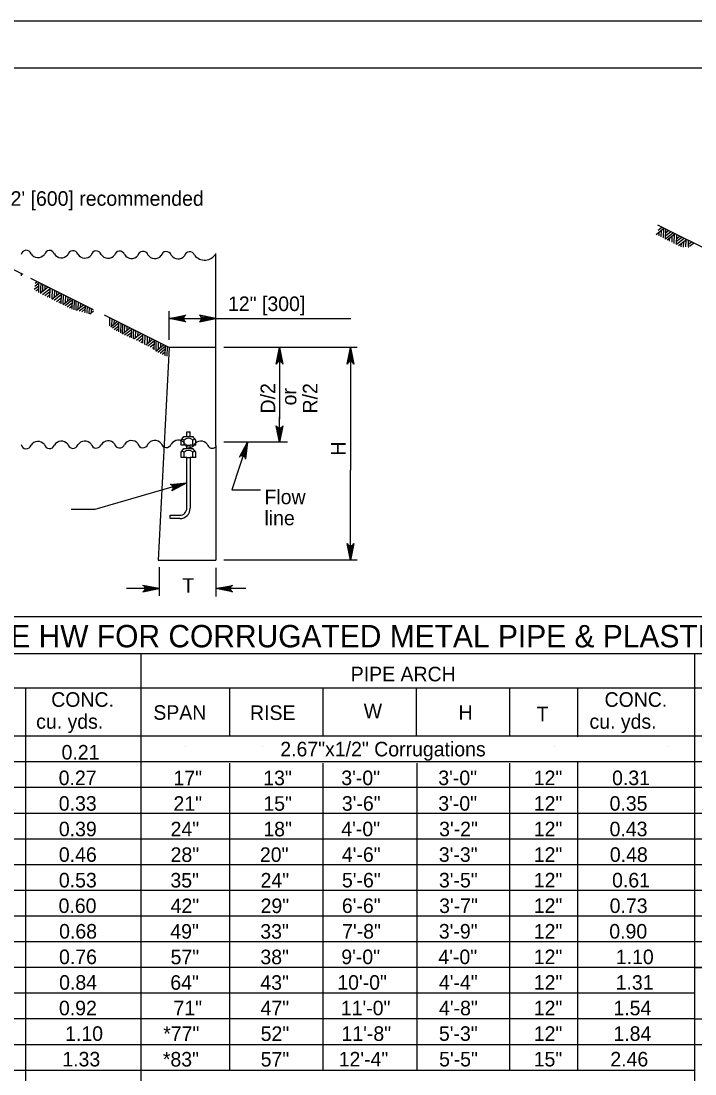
# Model space of a CAD drawing. Extents: x 1083.1 to 1117.1, y 675.4 to 741.4.
# Drawn here: x 1090.68 to 1097.9, y 730.07 to 741.35 of the extents above; entities that cross this region are included whole.
import ezdxf

# ---------------------------------------------------------------- set-up
doc = ezdxf.new("R2010")
doc.units = 0
doc.layers.add('Level 1', color=7, linetype='Continuous')

msp = doc.modelspace()

# ---------------------------------------------------------------- linework, layer by layer
at = {"layer": 'Level 1'}
for p, q in [((1097.48, 739.068), (1097.563, 739.135)), ((1098.803, 738.515), (1097.497, 739.168)), ((1097.503, 739.115), (1097.542, 739.146)), ((1097.534, 739.041), (1097.537, 739.114)), ((1097.558, 739.03), (1097.561, 739.133)), ((1097.579, 739.019), (1097.583, 739.126)), ((1097.581, 739.085), (1097.612, 739.11)), ((1097.511, 739.053), (1097.513, 739.095)), ((1097.579, 739.022), (1097.66, 739.086)), ((1097.58, 739.053), (1097.637, 739.098)), ((1097.597, 739.01), (1097.681, 739.076)), ((1097.624, 738.996), (1097.626, 739.032)), ((1097.65, 738.984), (1097.652, 739.053)), ((1097.674, 738.971), (1097.677, 739.073)), ((1097.698, 738.959), (1097.701, 739.066)), ((1097.698, 738.962), (1097.779, 739.027)), ((1097.699, 738.995), (1097.754, 739.039)), ((1097.701, 739.026), (1097.731, 739.051)), ((1097.721, 738.948), (1097.804, 739.014)), ((1097.773, 738.931), (1097.775, 738.991)), ((1097.798, 738.935), (1097.8, 739.011)), ((1097.825, 738.939), (1097.827, 739.003)), ((1090.698, 738.638), (1090.069, 738.953)), ((1097.748, 738.934), (1097.75, 738.971)), ((1097.824, 738.932), (1097.826, 738.933)), ((1097.825, 738.962), (1097.857, 738.988)), ((1097.836, 738.941), (1097.881, 738.976)), ((1092.764, 736.807), (1092.764, 738.863)), ((1090.681, 738.626), (1090.682, 738.646)), ((1091.452, 738.261), (1090.782, 738.596)), ((1090.823, 738.514), (1090.868, 738.55)), ((1090.827, 738.546), (1090.849, 738.563)), ((1090.865, 738.446), (1090.868, 738.553)), ((1090.888, 738.493), (1090.89, 738.542)), ((1090.818, 738.48), (1090.867, 738.519)), ((1090.833, 738.462), (1090.866, 738.488)), ((1090.881, 738.438), (1090.965, 738.505)), ((1090.887, 738.442), (1090.888, 738.493)), ((1090.907, 738.425), (1090.987, 738.488)), ((1090.909, 738.46), (1090.911, 738.532)), ((1090.932, 738.413), (1090.986, 738.456)), ((1090.933, 738.479), (1090.934, 738.52)), ((1090.984, 738.387), (1090.987, 738.493)), ((1091.007, 738.375), (1091.09, 738.442)), ((1091.009, 738.377), (1091.012, 738.481)), ((1091.031, 738.364), (1091.11, 738.427)), ((1091.035, 738.398), (1091.037, 738.468)), ((1091.059, 738.418), (1091.06, 738.457)), ((1091.107, 738.325), (1091.11, 738.432)), ((1090.956, 738.401), (1090.985, 738.424)), ((1091.055, 738.351), (1091.109, 738.394)), ((1091.081, 738.339), (1091.108, 738.361)), ((1091.126, 738.316), (1091.209, 738.383)), ((1091.128, 738.318), (1091.131, 738.421)), ((1091.147, 738.305), (1091.228, 738.37)), ((1091.152, 738.337), (1091.155, 738.41)), ((1091.171, 738.293), (1091.227, 738.339)), ((1091.178, 738.357), (1091.179, 738.398)), ((1091.225, 738.266), (1091.228, 738.373)), ((1091.246, 738.26), (1091.25, 738.362)), ((1091.265, 738.256), (1091.268, 738.353)), ((1091.271, 738.255), (1091.346, 738.314)), ((1091.289, 738.269), (1091.292, 738.341)), ((1091.314, 738.289), (1091.316, 738.329)), ((1091.194, 738.282), (1091.226, 738.308)), ((1091.298, 738.248), (1091.365, 738.301)), ((1091.326, 738.24), (1091.364, 738.27)), ((1091.354, 738.232), (1091.363, 738.24)), ((1091.363, 738.23), (1091.365, 738.304)), ((1091.385, 738.244), (1091.387, 738.294)), ((1091.385, 738.224), (1091.385, 738.244)), ((1091.406, 738.217), (1091.408, 738.283)), ((1091.412, 738.216), (1091.452, 738.248)), ((1091.43, 738.231), (1091.431, 738.271)), ((1092.263, 737.856), (1091.569, 738.202)), ((1092.263, 737.939), (1092.263, 738.245)), ((1091.626, 738.09), (1091.628, 738.173)), ((1091.638, 738.079), (1091.706, 738.134)), ((1091.649, 738.089), (1091.652, 738.161)), ((1091.655, 738.066), (1091.725, 738.121)), ((1091.675, 738.109), (1091.676, 738.149)), ((1091.675, 738.051), (1091.724, 738.09)), ((1091.722, 738.023), (1091.725, 738.124)), ((1091.744, 738.012), (1091.747, 738.114)), ((1091.762, 738.003), (1091.765, 738.104)), ((1091.786, 738.02), (1091.789, 738.093)), ((1092.423, 738.19), (1092.263, 738.168)), ((1092.417, 738.179), (1092.263, 738.168)), ((1092.263, 738.168), (1094.21, 738.168)), ((1092.416, 738.168), (1092.263, 738.168)), ((1092.418, 738.153), (1092.263, 738.168)), ((1092.425, 738.143), (1092.263, 738.168)), ((1092.601, 738.143), (1092.764, 738.168)), ((1092.603, 738.19), (1092.764, 738.168)), ((1092.608, 738.153), (1092.764, 738.168)), ((1092.609, 738.179), (1092.764, 738.168)), ((1092.61, 738.168), (1092.764, 738.168)), ((1091.696, 738.038), (1091.723, 738.06)), ((1091.764, 738.003), (1091.843, 738.066)), ((1091.786, 737.992), (1091.862, 738.053)), ((1091.811, 737.981), (1091.861, 738.022)), ((1091.812, 738.04), (1091.813, 738.081)), ((1091.834, 737.971), (1091.86, 737.991)), ((1091.859, 737.96), (1091.862, 738.056)), ((1091.881, 737.95), (1091.882, 737.996)), ((1091.882, 737.996), (1091.884, 738.045)), ((1091.885, 737.948), (1091.959, 738.008)), ((1091.903, 737.963), (1091.905, 738.035)), ((1091.911, 737.936), (1091.981, 737.991)), ((1091.927, 737.982), (1091.929, 738.023)), ((1091.979, 737.902), (1091.981, 737.996)), ((1092.003, 737.89), (1092.006, 737.984)), ((1091.936, 737.923), (1091.98, 737.959)), ((1091.96, 737.911), (1091.979, 737.927)), ((1092.011, 737.886), (1092.084, 737.945)), ((1092.029, 737.901), (1092.031, 737.971)), ((1092.034, 737.874), (1092.104, 737.93)), ((1092.053, 737.921), (1092.054, 737.96)), ((1092.059, 737.862), (1092.103, 737.897)), ((1092.083, 737.848), (1092.102, 737.864)), ((1092.102, 737.831), (1092.104, 737.935)), ((1092.12, 737.819), (1092.203, 737.886)), ((1092.122, 737.821), (1092.125, 737.924)), ((1092.141, 737.808), (1092.222, 737.873)), ((1092.147, 737.84), (1092.149, 737.913)), ((1092.172, 737.86), (1092.173, 737.901)), ((1092.219, 737.769), (1092.222, 737.876)), ((1092.241, 737.762), (1092.244, 737.865)), ((1092.263, 737.856), (1092.146, 735.578)), ((1092.165, 737.796), (1092.221, 737.842)), ((1092.188, 737.785), (1092.22, 737.811)), ((1092.764, 737.856), (1092.263, 737.856)), ((1094.277, 737.856), (1092.847, 737.856)), ((1093.421, 737.694), (1093.446, 737.856)), ((1093.431, 737.7), (1093.446, 737.856)), ((1093.446, 737.703), (1093.446, 737.856)), ((1093.457, 737.701), (1093.446, 737.856)), ((1093.468, 737.696), (1093.446, 737.856)), ((1093.446, 737.856), (1093.446, 737.089)), ((1094.18, 737.694), (1094.205, 737.856)), ((1094.191, 737.7), (1094.205, 737.856)), ((1094.205, 737.856), (1094.205, 736.544)), ((1094.205, 737.703), (1094.205, 737.856)), ((1094.216, 737.701), (1094.205, 737.856)), ((1094.227, 737.696), (1094.205, 737.856)), ((1093.446, 736.841), (1093.446, 737.112)), ((1093.423, 737.001), (1093.446, 736.841)), ((1093.434, 736.996), (1093.446, 736.841)), ((1093.47, 737.003), (1093.446, 736.841)), ((1093.46, 736.997), (1093.446, 736.841)), ((1093.446, 736.994), (1093.446, 736.841)), ((1092.392, 736.864), (1092.421, 736.904)), ((1092.392, 736.809), (1092.392, 736.864)), ((1092.421, 736.904), (1092.518, 736.904)), ((1092.422, 736.809), (1092.422, 736.865)), ((1092.452, 736.904), (1092.452, 736.952)), ((1092.452, 736.952), (1092.488, 736.952)), ((1092.488, 736.904), (1092.488, 736.952)), ((1092.548, 736.864), (1092.518, 736.904)), ((1092.518, 736.809), (1092.518, 736.865)), ((1092.548, 736.809), (1092.548, 736.864)), ((1092.452, 736.809), (1092.392, 736.809)), ((1092.392, 736.734), (1092.421, 736.774)), ((1092.392, 736.678), (1092.392, 736.734)), ((1092.421, 736.774), (1092.518, 736.774)), ((1092.422, 736.678), (1092.422, 736.735)), ((1092.452, 736.774), (1092.452, 736.809)), ((1092.452, 736.809), (1092.488, 736.809)), ((1092.488, 736.774), (1092.488, 736.809)), ((1092.548, 736.809), (1092.488, 736.809)), ((1092.548, 736.734), (1092.518, 736.774)), ((1092.518, 736.678), (1092.518, 736.735)), ((1092.548, 736.678), (1092.548, 736.734)), ((1092.764, 736.807), (1092.764, 736.518)), ((1093.529, 736.841), (1092.847, 736.841)), ((1093.029, 736.694), (1093.102, 736.841)), ((1093.041, 736.697), (1093.102, 736.841)), ((1093.056, 736.695), (1093.102, 736.841)), ((1093.066, 736.69), (1093.102, 736.841)), ((1093.075, 736.682), (1093.102, 736.841)), ((1092.452, 736.678), (1092.392, 736.678)), ((1092.452, 736.678), (1092.488, 736.678)), ((1092.452, 736.134), (1092.452, 736.678)), ((1092.548, 736.678), (1092.488, 736.678)), ((1092.488, 736.678), (1092.488, 736.134)), ((1092.764, 736.518), (1092.764, 735.578)), ((1094.205, 735.578), (1094.205, 736.544)), ((1092.289, 736.384), (1092.452, 736.406)), ((1092.298, 736.376), (1092.452, 736.406)), ((1092.304, 736.339), (1092.452, 736.406)), ((1092.305, 736.363), (1092.452, 736.406)), ((1092.306, 736.352), (1092.452, 736.406)), ((1092.272, 736.059), (1092.377, 736.059)), ((1092.272, 736.023), (1092.272, 736.059)), ((1092.377, 736.023), (1092.272, 736.023)), ((1094.183, 735.739), (1094.205, 735.578)), ((1094.194, 735.733), (1094.205, 735.578)), ((1094.23, 735.741), (1094.205, 735.578)), ((1094.219, 735.735), (1094.205, 735.578)), ((1094.205, 735.732), (1094.205, 735.578)), ((1092.146, 735.578), (1092.764, 735.578)), ((1092.157, 735.502), (1092.157, 735.196)), ((1092.764, 735.495), (1092.764, 735.19)), ((1094.277, 735.578), (1092.847, 735.578)), ((1092.157, 735.273), (1091.804, 735.273)), ((1091.995, 735.248), (1092.157, 735.273)), ((1091.997, 735.295), (1092.157, 735.273)), ((1092.001, 735.259), (1092.157, 735.273)), ((1092.002, 735.284), (1092.157, 735.273)), ((1092.004, 735.273), (1092.157, 735.273)), ((1092.924, 735.295), (1092.764, 735.273)), ((1092.918, 735.284), (1092.764, 735.273)), ((1093.085, 735.273), (1092.764, 735.273)), ((1092.917, 735.273), (1092.764, 735.273)), ((1092.92, 735.259), (1092.764, 735.273)), ((1092.926, 735.248), (1092.764, 735.273)), ((1086.66, 734.976), (1103.868, 734.976)), ((1103.868, 734.576), (1086.654, 734.576)), ((1091.964, 721.026), (1091.964, 734.576)), ((1097.894, 721.026), (1097.894, 734.576)), ((1103.868, 734.205), (1086.654, 734.205)), ((1090.728, 721.026), (1090.728, 734.205)), ((1092.913, 733.692), (1092.913, 734.205)), ((1093.913, 733.692), (1093.913, 734.205)), ((1094.912, 733.692), (1094.912, 734.205)), ((1095.912, 733.692), (1095.912, 734.205)), ((1096.642, 733.684), (1096.642, 734.203)), ((1103.868, 733.692), (1086.654, 733.692)), ((1103.868, 733.692), (1086.689, 733.692)), ((1092.437, 733.58), (1092.437, 733.58)), ((1093.265, 733.58), (1093.265, 733.58)), ((1094.26, 733.58), (1094.26, 733.58)), ((1094.386, 733.58), (1094.386, 733.58)), ((1094.407, 733.58), (1094.407, 733.58)), ((1095.265, 733.58), (1095.265, 733.58)), ((1095.39, 733.58), (1095.39, 733.58)), ((1095.412, 733.58), (1095.412, 733.58)), ((1096.396, 733.58), (1096.396, 733.58)), ((1097.604, 733.58), (1097.604, 733.58)), ((1103.868, 733.416), (1086.654, 733.416)), ((1092.913, 730.113), (1092.913, 733.404)), ((1093.913, 730.111), (1093.913, 733.404)), ((1094.918, 730.11), (1094.918, 733.404)), ((1095.912, 730.109), (1095.912, 733.404)), ((1096.642, 730.109), (1096.642, 733.415)), ((1103.868, 733.141), (1086.654, 733.141)), ((1103.868, 732.865), (1086.654, 732.865)), ((1103.868, 732.59), (1086.654, 732.59)), ((1103.868, 732.315), (1086.654, 732.315)), ((1103.868, 732.039), (1086.654, 732.039)), ((1103.868, 731.764), (1086.654, 731.764)), ((1103.868, 731.489), (1086.654, 731.489)), ((1103.868, 731.213), (1086.654, 731.213)), ((1097.894, 731.214), (1103.868, 731.213)), ((1097.894, 730.938), (1086.654, 730.938)), ((1097.894, 730.663), (1086.654, 730.663)), ((1097.894, 730.663), (1103.868, 730.663)), ((1103.868, 730.387), (1086.654, 730.387)), ((1091.981, 730.112), (1086.654, 730.112)), ((1091.966, 730.114), (1097.894, 730.113))]:
    msp.add_line(p, q, dxfattribs=at)
for points in [[(1083.126, 719.354), (1117.126, 719.354), (1117.126, 741.354), (1083.126, 741.354)], [(1085.126, 740.854), (1116.626, 740.854), (1116.626, 719.854), (1085.126, 719.854)]]:
    msp.add_lwpolyline(points, close=True, dxfattribs=at)
for points in [[(1092.439, 738.132), (1092.263, 738.168), (1092.439, 738.203)], [(1092.587, 738.132), (1092.764, 738.168), (1092.587, 738.203)], [(1093.41, 737.679), (1093.446, 737.856), (1093.481, 737.679)], [(1094.17, 737.679), (1094.205, 737.856), (1094.24, 737.679)], [(1093.481, 737.018), (1093.446, 736.841), (1093.41, 737.018)], [(1093.102, 736.841), (1092.933, 736.33), (1093.241, 736.33)], [(1093.015, 736.683), (1093.102, 736.841), (1093.082, 736.662)], [(1092.452, 736.406), (1091.467, 736.122), (1091.212, 736.122)], [(1092.272, 736.39), (1092.452, 736.406), (1092.292, 736.322)], [(1094.24, 735.755), (1094.205, 735.578), (1094.17, 735.755)], [(1091.98, 735.238), (1092.157, 735.273), (1091.98, 735.308)], [(1092.941, 735.238), (1092.764, 735.273), (1092.941, 735.308)]]:
    msp.add_lwpolyline(points, dxfattribs=at)
for centre, start, end in [((1092.454, 738.168), 112.0878, 247.9139), ((1092.572, 738.168), 292.0861, 67.9122), ((1093.446, 737.665), 22.0878, 157.9139), ((1094.205, 737.665), 22.0878, 157.9139), ((1093.446, 737.033), 202.0878, 337.9139), ((1093.044, 736.659), 4.3457, 140.1718), ((1092.268, 736.352), 308.4281, 84.2543), ((1094.205, 735.77), 202.0878, 337.9139), ((1091.966, 735.273), 292.0861, 67.9122), ((1092.955, 735.273), 112.0878, 247.9139)]:
    msp.add_arc(centre, 0.0382, start, end, dxfattribs=at)
for centre, major_axis, start_param, end_param in [((1090.731, 738.842), (0.056, 0), 0.338176, 2.936471), ((1090.981, 738.84), (0.056, 0), 0.338176, 2.936471), ((1091.231, 738.838), (0.056, 0), 0.338176, 2.936471), ((1091.481, 738.836), (0.056, 0), 0.338176, 2.936471), ((1091.732, 738.833), (0.056, 0), 0.338176, 2.936471), ((1091.982, 738.831), (0.056, 0), 0.338176, 2.936471), ((1092.232, 738.829), (0.056, 0), 0.338176, 2.936471), ((1092.482, 738.827), (0.056, 0), 0.338176, 2.936471), ((1090.858, 738.907), (0.0877, 0), 3.693284, 5.600053), ((1091.108, 738.905), (0.0877, 0), 3.693284, 5.600053), ((1091.359, 738.902), (0.0877, 0), 3.693284, 5.600053), ((1091.609, 738.9), (0.0877, 0), 3.693284, 5.600053), ((1091.859, 738.898), (0.0877, 0), 3.693284, 5.600053), ((1092.109, 738.896), (0.0877, 0), 3.693284, 5.600053), ((1092.36, 738.893), (0.0877, 0), 3.693284, 5.600053), ((1092.643, 738.932), (-0.139, 0), 0.676998, 2.618407), ((1090.858, 736.763), (0.0877, 0), 0.683132, 2.589902), ((1091.108, 736.765), (0.0877, 0), 0.683132, 2.589902), ((1091.359, 736.767), (0.0877, 0), 0.683132, 2.589902), ((1091.609, 736.769), (0.0877, 0), 0.683132, 2.589902), ((1091.859, 736.772), (0.0877, 0), 0.683132, 2.589902), ((1092.109, 736.774), (0.0877, 0), 0.683132, 2.589902), ((1092.36, 736.776), (0.0877, 0), 0.683132, 2.589902), ((1092.492, 736.773), (-0.139, 0), 5.437851, 5.606187), ((1092.403, 736.844), (0.0285, 0), 0.841371, 1.76551), ((1092.47, 736.812), (-0.0719, 0), 3.978969, 5.445809), ((1092.537, 736.844), (-0.0285, 0), 4.515292, 5.441815), ((1092.603, 736.766), (0.0877, 0), 0.683132, 2.589902), ((1090.731, 736.827), (0.056, 0), 3.346714, 5.94501), ((1090.981, 736.829), (0.056, 0), 3.346714, 5.94501), ((1091.231, 736.832), (0.056, 0), 3.346714, 5.94501), ((1091.481, 736.834), (0.056, 0), 3.346714, 5.94501), ((1091.732, 736.836), (0.056, 0), 3.346714, 5.94501), ((1091.982, 736.838), (0.056, 0), 3.346714, 5.94501), ((1092.232, 736.841), (0.056, 0), 3.346714, 5.94501), ((1092.403, 736.714), (0.0285, 0), 0.841371, 1.76551), ((1092.47, 736.681), (-0.0719, 0), 3.978969, 5.445809), ((1092.483, 736.843), (0.056, 0), 3.346714, 5.94501), ((1092.537, 736.714), (-0.0285, 0), 4.515292, 5.441815), ((1092.726, 736.833), (0.056, 0), 3.346714, 5.471643), ((1092.377, 736.134), (-0.075, 0), 1.570796, 3.141593), ((1092.377, 736.134), (0.111, 0), 4.71461, 6.280964)]:
    msp.add_ellipse(centre, major_axis=major_axis, ratio=0.999895, start_param=start_param, end_param=end_param, dxfattribs=at)

# ---------------------------------------------------------------- texts
for s, height, p in [("2' [600] recommended", 0.156, (1090.564, 739.375)), ('12" [300]', 0.156, (1092.893, 738.247)), ('Flow', 0.156, (1093.284, 736.178)), ('line', 0.156, (1093.284, 735.952)), ('T', 0.156, (1092.404, 735.229)), ('CAST IN PLACE HW FOR CORRUGATED METAL PIPE & PLASTIC PIPE (English)', 0.24, (1088.367, 734.644)), ('PIPE ARCH', 0.156, (1094.208, 734.28)), ('CONC.', 0.156, (1090.999, 734.007)), ('CONC.', 0.156, (1096.927, 734.007)), ('SPAN', 0.156, (1092.093, 733.868)), ('W', 0.156, (1094.347, 733.884)), ('cu. yds.', 0.156, (1090.838, 733.772)), ('RISE', 0.156, (1093.129, 733.866)), ('H', 0.156, (1095.363, 733.868)), ('T', 0.156, (1096.198, 733.851)), ('cu. yds.', 0.156, (1096.766, 733.772)), ('0.21', 0.156, (1091.11, 733.442)), ('2.67"x1/2" Corrugations', 0.156, (1093.453, 733.476)), ('0.27', 0.156, (1091.079, 733.168)), ('17"', 0.156, (1092.309, 733.167)), ('13"', 0.156, (1093.271, 733.167)), ('3\'-0"', 0.156, (1094.107, 733.168)), ('3\'-0"', 0.156, (1095.146, 733.168)), ('12"', 0.156, (1096.169, 733.168)), ('0.31', 0.156, (1097.008, 733.168)), ('0.33', 0.156, (1091.08, 732.894)), ('21"', 0.156, (1092.309, 732.893)), ('15"', 0.156, (1093.272, 732.893)), ('3\'-6"', 0.156, (1094.113, 732.894)), ('3\'-0"', 0.156, (1095.146, 732.894)), ('12"', 0.156, (1096.169, 732.894)), ('0.35', 0.156, (1096.981, 732.894)), ('0.39', 0.156, (1091.081, 732.62)), ('24"', 0.156, (1092.278, 732.619)), ('18"', 0.156, (1093.272, 732.619)), ('4\'-0"', 0.156, (1094.107, 732.62)), ('3\'-2"', 0.156, (1095.155, 732.62)), ('12"', 0.156, (1096.169, 732.62)), ('0.43', 0.156, (1096.981, 732.62)), ('0.46', 0.156, (1091.081, 732.346)), ('28"', 0.156, (1092.278, 732.345)), ('20"', 0.156, (1093.235, 732.345)), ('4\'-6"', 0.156, (1094.113, 732.346)), ('3\'-3"', 0.156, (1095.152, 732.346)), ('12"', 0.156, (1096.169, 732.346)), ('0.48', 0.156, (1096.984, 732.346)), ('0.53', 0.156, (1091.081, 732.072)), ('35"', 0.156, (1092.276, 732.071)), ('24"', 0.156, (1093.242, 732.071)), ('5\'-6"', 0.156, (1094.114, 732.072)), ('3\'-5"', 0.156, (1095.153, 732.072)), ('12"', 0.156, (1096.169, 732.072)), ('0.61', 0.156, (1097.008, 732.072)), ('0.60', 0.156, (1091.078, 731.798)), ('42"', 0.156, (1092.278, 731.797)), ('29"', 0.156, (1093.242, 731.797)), ('6\'-6"', 0.156, (1094.113, 731.798)), ('3\'-7"', 0.156, (1095.155, 731.798)), ('12"', 0.156, (1096.169, 731.798)), ('0.73', 0.156, (1096.982, 731.798)), ('0.68', 0.156, (1091.084, 731.524)), ('49"', 0.156, (1092.275, 731.523)), ('33"', 0.156, (1093.239, 731.523)), ('7\'-8"', 0.156, (1094.116, 731.524)), ('3\'-9"', 0.156, (1095.152, 731.524)), ('12"', 0.156, (1096.169, 731.524)), ('0.90', 0.156, (1096.978, 731.524)), ('0.76', 0.156, (1091.083, 731.25)), ('57"', 0.156, (1092.278, 731.249)), ('38"', 0.156, (1093.24, 731.249)), ('9\'-0"', 0.156, (1094.107, 731.25)), ('4\'-0"', 0.156, (1095.147, 731.25)), ('12"', 0.156, (1096.169, 731.25)), ('1.10', 0.156, (1097.048, 731.25)), ('0.84', 0.156, (1091.084, 730.976)), ('64"', 0.156, (1092.275, 730.975)), ('43"', 0.156, (1093.24, 730.975)), ('10\'-0"', 0.156, (1094.064, 730.976)), ('4\'-4"', 0.156, (1095.153, 730.976)), ('12"', 0.156, (1096.169, 730.976)), ('1.31', 0.156, (1097.046, 730.976)), ('0.92', 0.156, (1091.082, 730.702)), ('71"', 0.156, (1092.309, 730.701)), ('47"', 0.156, (1093.242, 730.701)), ('11\'-0"', 0.156, (1094.102, 730.702)), ('4\'-8"', 0.156, (1095.154, 730.702)), ('12"', 0.156, (1096.169, 730.702)), ('1.54', 0.156, (1097.022, 730.702)), ('1.10', 0.156, (1091.148, 730.428)), ('*77"', 0.156, (1092.199, 730.427)), ('52"', 0.156, (1093.243, 730.427)), ('11\'-8"', 0.156, (1094.109, 730.428)), ('5\'-3"', 0.156, (1095.153, 730.428)), ('12"', 0.156, (1096.169, 730.428)), ('1.84', 0.156, (1097.022, 730.428)), ('1.33', 0.156, (1091.118, 730.154)), ('*83"', 0.156, (1092.195, 730.153)), ('57"', 0.156, (1093.243, 730.153)), ('12\'-4"', 0.156, (1094.079, 730.154)), ('5\'-5"', 0.156, (1095.155, 730.154)), ('15"', 0.156, (1096.168, 730.154)), ('2.46', 0.156, (1096.989, 730.154))]:
    msp.add_text(s, height=height, dxfattribs=at).set_placement(p)
for s, p in [('D/2', (1093.399, 737.15)), ('or', (1093.625, 737.236)), ('R/2', (1093.851, 737.15)), ('H', (1094.152, 736.698))]:
    msp.add_text(s, height=0.156, rotation=90, dxfattribs=at).set_placement(p)

doc.saveas('drawing.dxf')
